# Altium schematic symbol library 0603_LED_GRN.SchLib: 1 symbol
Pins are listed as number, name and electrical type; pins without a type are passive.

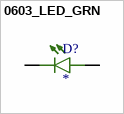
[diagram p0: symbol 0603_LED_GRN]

## 0603_LED_GRN
designator D?
MF: Wurth Elektronik; MP: 150060VS75000
footprint 0603_LED
pins: 1 NEG, 2 POS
